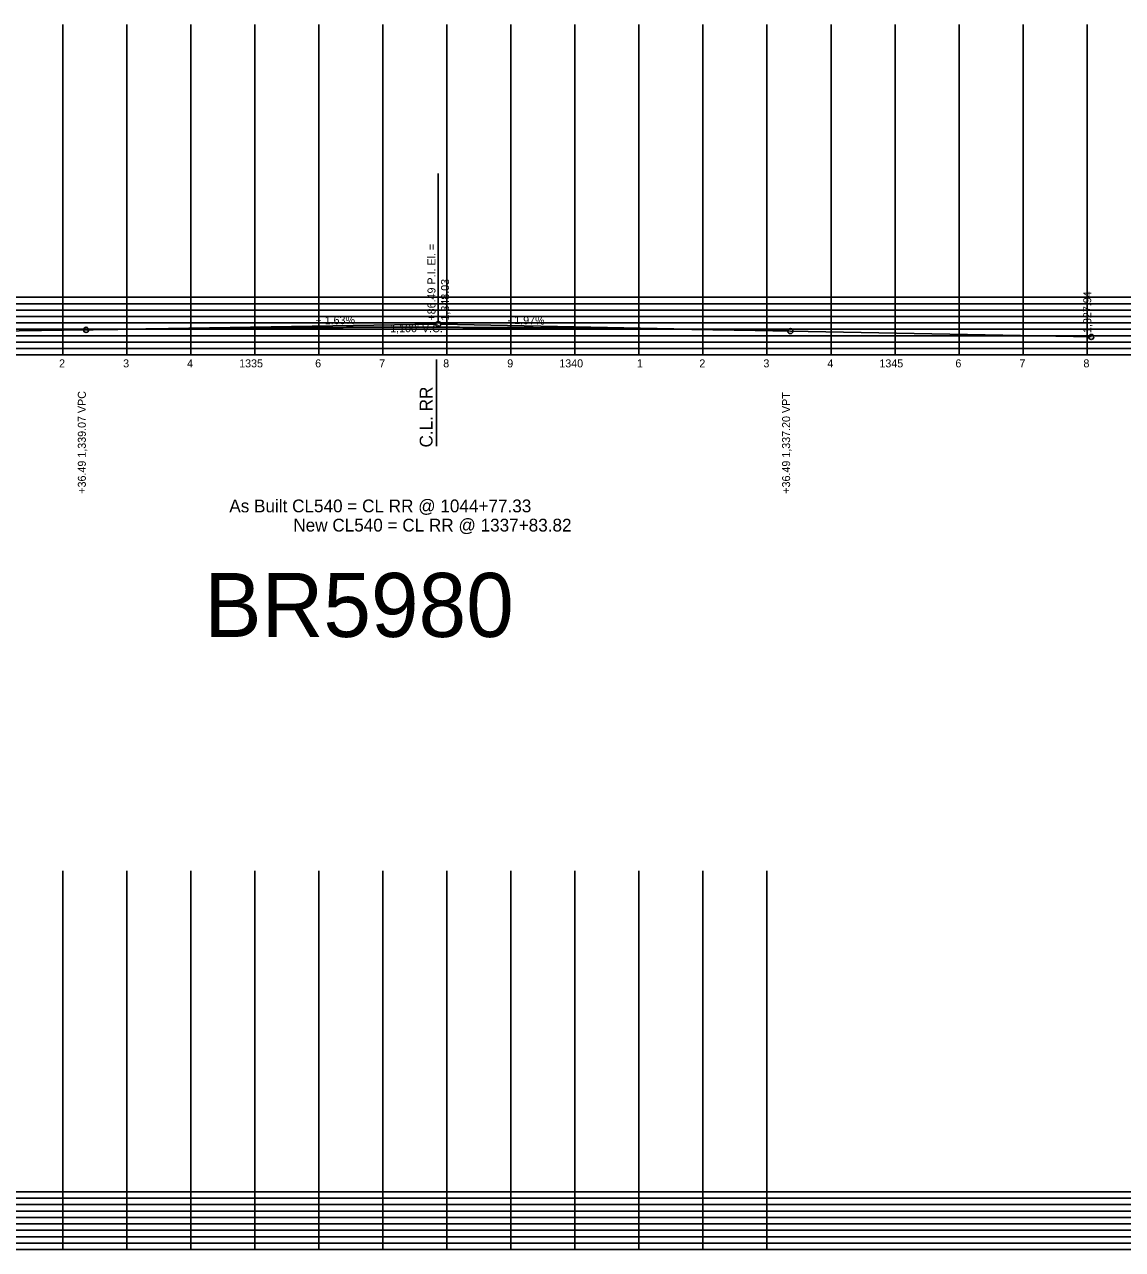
# Model space of a CAD drawing. Extents: x 680639 to 702326, y 743523 to 756592.
# Drawn here: x 689366 to 691081, y 743777 to 745690 of the extents above; entities that cross this region are included whole.
import ezdxf

# ---------------------------------------------------------------- set-up
doc = ezdxf.new("R2010")
doc.units = 0
for name, color, linetype in [('Default', 7, 'Continuous'), ('R_Grid', 7, 'Continuous'), ('R_Proposed Road', 7, 'Continuous')]:
    doc.layers.add(name, color=color, linetype=linetype)

msp = doc.modelspace()

# ---------------------------------------------------------------- linework, layer by layer
at = {"layer": 'Default'}
for p, q in [((690012.2, 745226.1), (690012.2, 745457.5)), ((689032.2, 745206.1), (689462.2, 745213.1)), ((689462.2, 745213.1), (690008.2, 745222)), ((690562.2, 745211.2), (690016.2, 745222)), ((690562.2, 745211.2), (691032.2, 745202)), ((680725.7, 745174), (702325.7, 745174)), ((680725.7, 743776.7), (702325.7, 743776.7))]:
    msp.add_line(p, q, dxfattribs=at)
for centre in [(689462.2, 745213.1), (690012.2, 745222.1), (690562.2, 745211.2), (691032.2, 745202)]:
    msp.add_circle(centre, 4, dxfattribs=at)
msp.add_spline([(689462.2, 745213.1), (689484.2, 745213.5), (689506.2, 745213.8), (689528.2, 745214.1), (689550.2, 745214.4), (689572.2, 745214.7), (689594.2, 745215), (689616.2, 745215.2), (689638.2, 745215.5), (689660.2, 745215.7), (689682.2, 745215.9), (689704.2, 745216.1), (689726.2, 745216.3), (689748.2, 745216.4), (689770.2, 745216.6), (689792.2, 745216.7), (689814.2, 745216.8), (689836.2, 745216.9), (689858.2, 745217), (689880.2, 745217.1), (689902.2, 745217.1), (689924.2, 745217.1), (689946.2, 745217.2), (689968.2, 745217.2), (689990.2, 745217.1), (690012.2, 745217.1), (690034.2, 745217.1), (690056.2, 745217), (690078.2, 745216.9), (690100.2, 745216.8), (690122.2, 745216.7), (690144.2, 745216.6), (690166.2, 745216.5), (690188.2, 745216.3), (690210.2, 745216.1), (690232.2, 745215.9), (690254.2, 745215.7), (690276.2, 745215.5), (690298.2, 745215.3), (690320.2, 745215), (690342.2, 745214.8), (690364.2, 745214.5), (690386.2, 745214.2), (690408.2, 745213.9), (690430.2, 745213.5), (690452.2, 745213.2), (690474.2, 745212.8), (690496.2, 745212.5), (690518.2, 745212.1), (690540.2, 745211.7), (690562.2, 745211.2)], degree=3, dxfattribs=at)
at = {"layer": 'R_Grid'}
for p, q in [((689425.7, 745174), (689425.7, 745690.1)), ((689525.7, 745174), (689525.7, 745690.1)), ((689625.7, 745174), (689625.7, 745690.1)), ((689725.7, 745174), (689725.7, 745690.1)), ((689825.7, 745174), (689825.7, 745690.1)), ((689925.7, 745174), (689925.7, 745690.1)), ((690025.7, 745174), (690025.7, 745690.1)), ((690125.7, 745174), (690125.7, 745690.1)), ((690225.7, 745174), (690225.7, 745690.1)), ((690325.7, 745174), (690325.7, 745690.1)), ((690425.7, 745174), (690425.7, 745690.1)), ((690525.7, 745174), (690525.7, 745690.1)), ((690625.7, 745174), (690625.7, 745690.1)), ((690725.7, 745174), (690725.7, 745690.1)), ((690825.7, 745174), (690825.7, 745690.1)), ((690925.7, 745174), (690925.7, 745690.1)), ((691025.7, 745174), (691025.7, 745690.1)), ((680725.7, 745264), (695445.5, 745264)), ((680725.7, 745254), (695445.5, 745254)), ((680725.7, 745244), (695445.5, 745244)), ((680725.7, 745234), (695445.5, 745234)), ((680725.7, 745224), (695445.5, 745224)), ((680725.7, 745214), (695445.5, 745214)), ((680725.7, 745204), (695445.5, 745204)), ((680725.7, 745194), (695445.5, 745194)), ((680725.7, 745184), (695445.5, 745184)), ((680725.7, 745174), (695445.5, 745174)), ((689425.7, 743776.7), (689425.7, 744368.3)), ((689525.7, 743776.7), (689525.7, 744368.3)), ((689625.7, 743776.7), (689625.7, 744368.3)), ((689725.7, 743776.7), (689725.7, 744368.3)), ((689825.7, 743776.7), (689825.7, 744368.3)), ((689925.7, 743776.7), (689925.7, 744368.3)), ((690025.7, 743776.7), (690025.7, 744368.3)), ((690125.7, 743776.7), (690125.7, 744368.3)), ((690225.7, 743776.7), (690225.7, 744368.3)), ((690325.7, 743776.7), (690325.7, 744368.3)), ((690425.7, 743776.7), (690425.7, 744368.3)), ((690525.7, 743776.7), (690525.7, 744368.3)), ((680725.7, 743866.7), (694315.6, 743866.7)), ((680725.7, 743856.7), (694315.6, 743856.7)), ((680725.7, 743846.7), (694315.6, 743846.7)), ((680725.7, 743836.7), (694315.6, 743836.7)), ((680725.7, 743826.7), (694315.6, 743826.7)), ((680725.7, 743816.7), (694315.6, 743816.7)), ((680725.7, 743806.7), (694315.6, 743806.7)), ((680725.7, 743796.7), (694315.6, 743796.7)), ((680725.7, 743786.7), (694315.6, 743786.7)), ((680725.7, 743776.7), (694315.6, 743776.7))]:
    msp.add_line(p, q, dxfattribs=at)
at = {"layer": 'R_Proposed Road'}
msp.add_line((690009.6, 745167), (690009.6, 745031.3), dxfattribs=at)

# ---------------------------------------------------------------- texts
at = {"layer": 'Default'}
for s, rotation, p in [('+86.49 P.I. El. = ', 90, (690007.9, 745227.6)), ('1,348.03', 90, (690029.1, 745227.6)), ('1,327.94', 90, (691032.2, 745208.2)), ('+ 1.63%', 0.9338, (689820.5, 745221.4)), ('- 1.97%', 358.8714, (690120.6, 745222.4)), ('+36.49 1,339.07 VPC ', 90, (689461.8, 744957.2)), ('+36.49 1,337.20 VPT ', 90, (690561.8, 744957.2))]:
    msp.add_text(s, height=12.5, rotation=rotation, dxfattribs=at).set_placement(p)
for s, p in [("1,100' V.C. ", (689937.2, 745209.4)), ('2', (689420, 745154.5)), ('3', (689520.1, 745154.5)), ('4', (689620, 745154.5)), ('1335', (689701.3, 745154.5)), ('6', (689820, 745154.5)), ('7', (689920, 745154.5)), ('8', (690020, 745154.5)), ('9', (690120, 745154.5)), ('1340', (690201.3, 745154.5)), ('1', (690322.5, 745154.5)), ('2', (690420, 745154.5)), ('3', (690520.1, 745154.5)), ('4', (690620, 745154.5)), ('1345', (690701.3, 745154.5)), ('6', (690820, 745154.5)), ('7', (690920, 745154.5)), ('8', (691020, 745154.5))]:
    msp.add_text(s, height=12.5, dxfattribs=at).set_placement(p)
at = {"layer": 'R_Proposed Road'}
msp.add_text('C.L. RR', height=20, rotation=90, dxfattribs=at).set_placement((690003.3, 745029.4))
for s, height, p in [('As Built CL540 = CL RR @ 1044+77.33', 20, (689685.9, 744928.1)), ('New CL540 = CL RR @ 1337+83.82', 20, (689785.9, 744898.1)), ('BR5980', 100, (689647, 744733.4))]:
    msp.add_text(s, height=height, dxfattribs=at).set_placement(p)

doc.saveas('drawing.dxf')
